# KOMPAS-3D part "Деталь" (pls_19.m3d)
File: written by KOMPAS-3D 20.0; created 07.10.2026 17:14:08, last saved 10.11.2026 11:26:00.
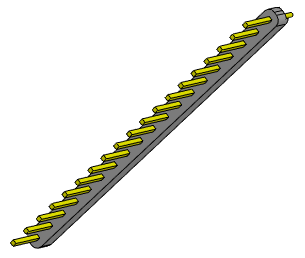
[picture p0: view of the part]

Document properties: Полное имя файла: D:\myProjects\Progect_esp32\box_compas\разъемы\pls_19.m3d

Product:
- Part/product: Деталь
    Масса: 0.0024606
  - Body: Тело 1
      Масса: 0.00247668

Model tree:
1. Эскиз:1
2. Элемент выдавливания:1
     Расстояние 1 = 2.5
3. Эскиз:2  (with: Элемент выдавливания:1)
4. Элемент выдавливания:2
     Расстояние 1 = 6
5. Массив по сетке:1  (with: Элемент выдавливания:2, Эскиз:2)  (19 pattern instances)
     Шаг 1 = 2.54; Угол раствора = 90
6. Эскиз:3  (with: Элемент выдавливания:1)
7. Элемент выдавливания:3
     Расстояние 1 = 3
8. Массив по сетке:2  (with: Элемент выдавливания:3, Эскиз:3)  (19 pattern instances)
     Шаг 1 = 2.54; Угол раствора = 90; Геометрический массив = 128
9. Эскиз:4  (with: Элемент выдавливания:1)
10. Элемент выдавливания:4
11. Скругление:1  (with: Элемент выдавливания:1)
     Радиус = 1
